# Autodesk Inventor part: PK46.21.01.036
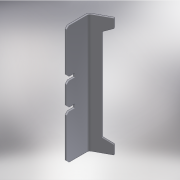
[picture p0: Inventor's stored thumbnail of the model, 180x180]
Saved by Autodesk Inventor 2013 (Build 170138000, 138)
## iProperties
Created: 2005-04
Part Number: PK46.21.01.036
Material: Steel, Mild
Document SubType Name: Sheet Metal
Designer: salex
Manufacturer: Standard
Standards Organization: Custom
Density: 7.86 g/cm^3
Sheet Metal Rule: Default
Author: salex
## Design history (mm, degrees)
node "ФлнОтгиб1"
sketch "Эскиз2"
  geometry: L1 (0, 0)-(800, 0) reference; L2 (800, 0)-(800, 138.127) reference; L3 (297, 0)-(322, 0); L4 (322, 0)-(322, 55); L5 (322, 55)-(297, 55); L6 (297, 55)-(297, 0); L7 (477, 0)-(502, 0); L8 (502, 0)-(502, 55); L9 (502, 55)-(477, 55); L10 (477, 55)-(477, 0)
  constraints: 16 end point, 4 parallel, 2 collinear, 2 horizontal, 2 perpendicular, 2 point on line
  dimensions: "d10" = 298 distance between parallel lines of L8 L2; "d11" = 25 distance of L8.end L9.end; "d12" = 55 distance of L7.end L8.end; "d13" = 180 distance between parallel lines of L4 L8
extrude "Выдавливание1" cut sketch "Эскиз2" stored distance "d14" = 10; taper "d15" = 0 deg
feature "Угловая фаска1" dims "d16" = 15, "d17" = 6, angle "d18" = 45 deg
sketch "Эскиз3"
  geometry: L1 (-113.427, 0)-(0, 0) reference; L2 (0, 800)-(0, 0) reference; L3 (0, 800)-(-113.427, 800) reference; L4 (0, 740)-(-60, 710); L5 (-60, 710)-(-60, 90); L6 (-60, 90)-(0, 60)
  constraints: 6 end point, 2 point on line, 1 equal length, 1 perpendicular
  dimensions: "d19" = 60 distance from line of L4.start L3; "d20" = 60 distance from line of L6.end L1; "d21" = 90 distance from line of L4.end L3; "d22" = 60 distance between parallel lines of L2 L5
extrude "Выдавливание2" cut sketch "Эскиз3" stored distance "d23" = 10; taper "d24" = 0 deg
body "Solid1"
sketch "Эскиз1"
  geometry: L1 (0, 0)-(0, 150); L2 (0, 150)-(110, 210)
  constraints: 4 end point, 1 vertical, 1 other
  dimensions: "d0" = 150 distance of L1.start L1.end; "d1" = 210 vertical distance of L2.end L1.start; "d2" = 110 horizontal distance of L1.end L2.end
feature "Плакирование1" dims "d3" = 800, "d4" = 10 (= BendReliefWidth), "d6" = 20 (= MinimumRemnant), "d8" = 20 (= BendRadius), "d9" = 10, "Thickness" = 10
feature "Изгиб1" dims "d4" = 10 (= BendReliefWidth), "d5" = 5 (= BendReliefDepth), "d6" = 20 (= MinimumRemnant), "d7" = 20 (= BendRadius), "d8" = 20 (= BendRadius), "d9" = 10, "SeamGap" = 0.01, "Thickness" = 10
other parameters: "BendRadius" = 20, "BendReliefDepth" = 5 (= 0.5 x Thickness)
